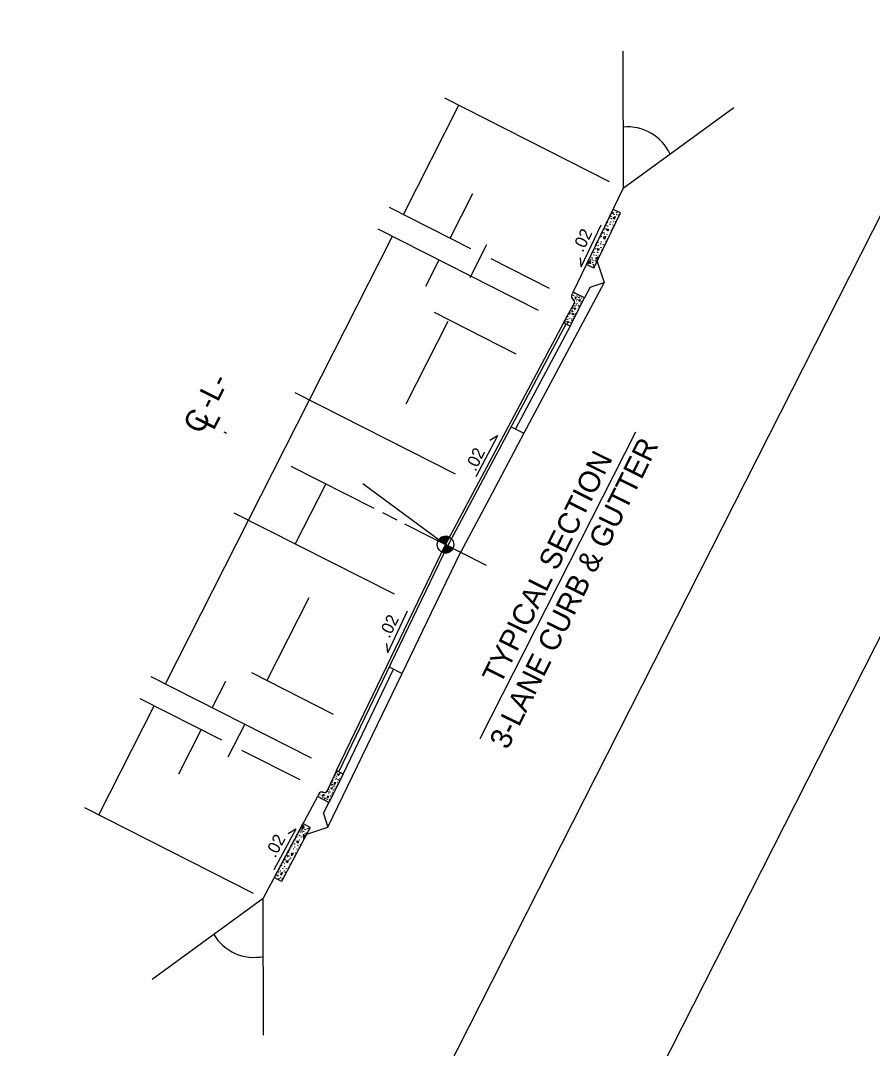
# Model space of a CAD drawing. Extents: x 1974386 to 1979988, y 776712 to 784860.
# Drawn here: x 1977212 to 1977629, y 778805 to 779309 of the extents above; entities that cross this region are included whole.
import ezdxf

# ---------------------------------------------------------------- set-up
doc = ezdxf.new("R2010")
doc.units = 0
for name, color, linetype in [('Default', 7, 'Continuous'), ('Old_Level_1', 7, 'Continuous'), ('Old_Level_2', 7, 'Continuous'), ('Old_Level_4', 7, 'Continuous')]:
    doc.layers.add(name, color=color, linetype=linetype)

msp = doc.modelspace()

# ---------------------------------------------------------------- linework, layer by layer
at = {"layer": 'Default'}
msp.add_lwpolyline([(1978009.96, 784859.92), (1974385.88, 777715.09), (1976364.02, 776711.71), (1979988.11, 783856.54)], close=True, dxfattribs=at)
at = {"layer": 'Old_Level_1'}
for p, q in [((1977506.9, 779294.21), (1977507.03, 779226.87)), ((1977419.44, 779271.28), (1977500.16, 779230.36)), ((1977399.38, 779214.18), (1977426.52, 779267.69)), ((1977561.2, 779266.39), (1977507.03, 779226.87)), ((1977482.53, 779176.05), (1977507.03, 779226.87)), ((1977422.32, 779202.55), (1977433.4, 779224.41)), ((1977392.3, 779217.77), (1977432.24, 779197.52)), ((1977489.03, 779189.57), (1977502.04, 779216.61)), ((1977492.71, 779187.8), (1977505.71, 779214.85)), ((1977505.71, 779214.85), (1977502.04, 779216.61)), ((1977386.88, 779207.07), (1977465.34, 779167.28)), ((1977353.26, 779123.21), (1977393.96, 779203.48)), ((1977432.06, 779183.23), (1977440.28, 779199.45)), ((1977410.39, 779179.02), (1977416.89, 779191.85)), ((1977442.18, 779192.48), (1977470.77, 779177.99)), ((1977492.71, 779187.8), (1977489.03, 779189.57)), ((1977494.3, 779191.12), (1977497.7, 779180.75)), ((1977497.7, 779180.75), (1977458.38, 779106.9)), ((1977490.91, 779178.53), (1977497.7, 779180.75)), ((1977481.82, 779174.66), (1977482.53, 779176.05)), ((1977488.09, 779173.23), (1977482.53, 779176.05)), ((1977490.91, 779178.53), (1977488.09, 779173.23)), ((1977477.81, 779160.96), (1977483.04, 779170.5)), ((1977481.04, 779159.32), (1977488.09, 779173.23)), ((1977414.4, 779166.2), (1977454.49, 779145.88)), ((1977400.68, 779121.35), (1977421.2, 779161.83)), ((1977477.81, 779160.96), (1977420, 779052.37)), ((1977478.92, 779160.37), (1977421.06, 779051.94)), ((1977481.04, 779159.32), (1977454.25, 779109)), ((1977481.04, 779159.32), (1977477.81, 779160.96)), ((1977346.18, 779126.8), (1977424.64, 779087.01)), ((1977323.41, 779064.34), (1977353.26, 779123.21)), ((1977452.09, 779110.09), (1977458.38, 779106.9)), ((1977312.79, 779106.73), (1977311.45, 779107.4)), ((1977436.95, 778957.34), (1977513.18, 779107.62)), ((1977458.38, 779106.9), (1977442.79, 779077.62)), ((1977344.18, 779090.81), (1977384.8, 779070.21)), ((1977361.27, 779082.15), (1977346.34, 779052.71)), ((1977379.4, 779082.27), (1977420, 779052.37)), ((1977442.79, 779077.62), (1977427.28, 779048.49)), ((1977282.71, 778984.07), (1977323.41, 779064.34)), ((1977316.33, 779067.93), (1977394.79, 779028.15)), ((1977389.02, 779068.07), (1977396.06, 779064.5)), ((1977399.9, 779062.55), (1977439.93, 779042.26)), ((1977420, 779052.37), (1977416.38, 779054.2)), ((1977421.83, 779055.98), (1977420, 779052.37)), ((1977366.57, 778941.55), (1977420, 779052.37)), ((1977367.69, 778940.98), (1977421.06, 779051.94)), ((1977413.09, 779019.05), (1977427.43, 779048.78)), ((1977418.17, 779048.75), (1977420, 779052.37)), ((1977423.6, 779050.53), (1977420, 779052.37)), ((1977420, 779052.37), (1977423.6, 779050.53)), ((1977352.97, 779026.24), (1977332.45, 778985.76)), ((1977398.69, 778989.17), (1977413.09, 779019.05)), ((1977324.86, 778989.6), (1977364.95, 778969.28)), ((1977362.35, 778913.82), (1977398.69, 778989.17)), ((1977369.79, 778939.91), (1977394.55, 778991.27)), ((1977392.4, 778992.36), (1977398.69, 778989.17)), ((1977275.63, 778987.66), (1977354.09, 778947.87)), ((1977312.14, 778985.27), (1977305.64, 778972.44)), ((1977250.15, 778919.85), (1977277.28, 778973.37)), ((1977270.2, 778976.96), (1977310.14, 778956.71)), ((1977321.59, 778964.35), (1977313.37, 778948.14)), ((1977300.22, 778961.74), (1977289.13, 778939.88)), ((1977320.08, 778951.67), (1977348.67, 778937.17)), ((1977366.57, 778941.55), (1977361.96, 778931.7)), ((1977369.79, 778939.91), (1977362.74, 778926.01)), ((1977369.79, 778939.91), (1977366.57, 778941.55)), ((1977357.18, 778928.83), (1977330.66, 778879.03)), ((1977357.88, 778930.22), (1977357.18, 778928.83)), ((1977362.74, 778926.01), (1977357.18, 778928.83)), ((1977243.07, 778923.44), (1977325.78, 778881.51)), ((1977360.13, 778920.6), (1977362.74, 778926.01)), ((1977360.13, 778920.6), (1977362.35, 778913.82)), ((1977350.11, 778915.59), (1977335.99, 778889.12)), ((1977353.71, 778913.67), (1977339.58, 778887.2)), ((1977353.71, 778913.67), (1977350.11, 778915.59)), ((1977351.98, 778910.42), (1977362.35, 778913.82)), ((1977339.58, 778887.2), (1977335.98, 778889.12)), ((1977276.26, 778839.34), (1977330.66, 778879.03)), ((1977330.8, 778811.97), (1977330.66, 778879.03))]:
    msp.add_line(p, q, dxfattribs=at)
for points in [[(1977416.4, 779054.23), (1977416.4, 779054.23), (1977420.01, 779052.4)], [(1977416.44, 779054.3), (1977420.05, 779052.47)], [(1977416.48, 779054.37), (1977420.09, 779052.54)], [(1977416.52, 779054.44), (1977420.12, 779052.62)], [(1977416.56, 779054.51), (1977420.16, 779052.69)], [(1977416.61, 779054.58), (1977420.2, 779052.76)], [(1977416.65, 779054.65), (1977420.23, 779052.83)], [(1977416.7, 779054.72), (1977420.27, 779052.9)], [(1977416.74, 779054.78), (1977420.31, 779052.98)], [(1977416.79, 779054.85), (1977420.34, 779053.05)], [(1977416.85, 779054.91), (1977420.38, 779053.12)], [(1977416.9, 779054.98), (1977420.42, 779053.19)], [(1977416.95, 779055.04), (1977420.45, 779053.27)], [(1977417.01, 779055.1), (1977420.49, 779053.34)], [(1977417.07, 779055.16), (1977420.53, 779053.41)], [(1977417.13, 779055.22), (1977420.56, 779053.48)], [(1977417.19, 779055.28), (1977420.6, 779053.55)], [(1977417.25, 779055.34), (1977420.64, 779053.63)], [(1977417.32, 779055.4), (1977420.67, 779053.7)], [(1977417.39, 779055.46), (1977420.71, 779053.77)], [(1977417.45, 779055.51), (1977420.75, 779053.84)], [(1977417.52, 779055.57), (1977420.78, 779053.92)], [(1977417.59, 779055.62), (1977420.82, 779053.99)], [(1977417.67, 779055.68), (1977420.86, 779054.06)], [(1977417.75, 779055.73), (1977420.89, 779054.13)], [(1977417.82, 779055.78), (1977420.93, 779054.2)], [(1977417.9, 779055.83), (1977420.97, 779054.28)], [(1977417.98, 779055.88), (1977421, 779054.35)], [(1977418.07, 779055.93), (1977421.04, 779054.42)], [(1977418.16, 779055.97), (1977421.08, 779054.49)], [(1977418.25, 779056.02), (1977421.11, 779054.57)], [(1977418.34, 779056.06), (1977421.15, 779054.64)], [(1977418.44, 779056.1), (1977421.19, 779054.71)], [(1977418.54, 779056.14), (1977421.22, 779054.78)], [(1977418.64, 779056.18), (1977421.26, 779054.86)], [(1977418.75, 779056.22), (1977421.29, 779054.93)], [(1977418.86, 779056.25), (1977421.33, 779055)], [(1977418.98, 779056.28), (1977421.37, 779055.07)], [(1977419.1, 779056.31), (1977421.4, 779055.14)], [(1977419.23, 779056.34), (1977421.44, 779055.22)], [(1977419.36, 779056.36), (1977421.48, 779055.29)], [(1977419.5, 779056.38), (1977421.51, 779055.36)], [(1977419.65, 779056.4), (1977421.55, 779055.43)], [(1977419.81, 779056.41), (1977421.59, 779055.51)], [(1977419.97, 779056.42), (1977421.62, 779055.58)], [(1977420.16, 779056.41), (1977421.66, 779055.65)], [(1977420.37, 779056.4), (1977421.7, 779055.72)], [(1977420.6, 779056.37), (1977421.73, 779055.79)], [(1977420.89, 779056.31), (1977421.77, 779055.87)], [(1977421.29, 779056.2), (1977421.81, 779055.94)], [(1977418.17, 779048.77), (1977418.57, 779048.57)], [(1977418.21, 779048.84), (1977419.03, 779048.43)], [(1977418.25, 779048.92), (1977419.32, 779048.37)], [(1977418.28, 779048.99), (1977419.58, 779048.33)], [(1977418.32, 779049.06), (1977419.78, 779048.32)], [(1977418.36, 779049.13), (1977419.97, 779048.31)], [(1977418.39, 779049.2), (1977420.14, 779048.32)], [(1977418.43, 779049.28), (1977420.31, 779048.32)], [(1977418.47, 779049.35), (1977420.46, 779048.34)], [(1977418.5, 779049.42), (1977420.6, 779048.36)], [(1977418.54, 779049.49), (1977420.73, 779048.38)], [(1977418.58, 779049.57), (1977420.86, 779048.41)], [(1977418.61, 779049.64), (1977420.98, 779048.44)], [(1977418.65, 779049.71), (1977421.1, 779048.47)], [(1977418.69, 779049.78), (1977421.21, 779048.5)], [(1977418.72, 779049.85), (1977421.32, 779048.54)], [(1977418.76, 779049.93), (1977421.42, 779048.58)], [(1977418.8, 779050), (1977421.53, 779048.61)], [(1977418.83, 779050.07), (1977421.63, 779048.65)], [(1977418.87, 779050.14), (1977421.72, 779048.7)], [(1977418.91, 779050.22), (1977421.81, 779048.74)], [(1977418.94, 779050.29), (1977421.9, 779048.79)], [(1977418.98, 779050.36), (1977421.98, 779048.84)], [(1977419.02, 779050.43), (1977422.07, 779048.89)], [(1977419.05, 779050.5), (1977422.15, 779048.93)], [(1977419.09, 779050.58), (1977422.23, 779048.99)], [(1977419.13, 779050.65), (1977422.3, 779049.04)], [(1977419.16, 779050.72), (1977422.38, 779049.09)], [(1977419.2, 779050.79), (1977422.45, 779049.15)], [(1977419.24, 779050.87), (1977422.52, 779049.2)], [(1977419.27, 779050.94), (1977422.59, 779049.26)], [(1977419.31, 779051.01), (1977422.66, 779049.31)], [(1977419.35, 779051.08), (1977422.72, 779049.37)], [(1977419.38, 779051.15), (1977422.79, 779049.43)], [(1977419.42, 779051.23), (1977422.85, 779049.49)], [(1977419.46, 779051.3), (1977422.91, 779049.55)], [(1977419.49, 779051.37), (1977422.96, 779049.61)], [(1977419.53, 779051.44), (1977423.02, 779049.67)], [(1977419.57, 779051.52), (1977423.07, 779049.74)], [(1977419.6, 779051.59), (1977423.13, 779049.8)], [(1977419.64, 779051.66), (1977423.18, 779049.87)], [(1977419.68, 779051.73), (1977423.23, 779049.93)], [(1977419.71, 779051.8), (1977423.28, 779050)], [(1977419.75, 779051.88), (1977423.33, 779050.06)], [(1977419.78, 779051.95), (1977423.37, 779050.13)], [(1977419.82, 779052.02), (1977423.42, 779050.2)], [(1977419.86, 779052.09), (1977423.46, 779050.27)], [(1977419.89, 779052.17), (1977423.5, 779050.34)], [(1977419.93, 779052.24), (1977423.54, 779050.41)], [(1977419.97, 779052.31), (1977423.58, 779050.48), (1977423.58, 779050.48)]]:
    msp.add_lwpolyline(points, dxfattribs=at)
msp.add_circle((1977419.99, 779052.36), 4.05, dxfattribs=at)
for centre, radius, start, end in [((1977509.22, 779234.09), 22.94, 24.6899, 95.6239), ((1977483.21, 779173.95), 1.56, 153.1133, 240.3562), ((1977481.67, 779171.24), 1.56, 331.2849, 60.3562), ((1977419.99, 779052.36), 4.05, 63.1038, 153.1038), ((1977419.99, 779052.36), 4.05, 243.1038, 333.1038), ((1977359.27, 778929.51), 1.56, 65.8705, 153.1133), ((1977360.55, 778932.36), 1.56, 245.8705, 334.9418), ((1977326.13, 778872.99), 22.94, 210.6027, 281.5371)]:
    msp.add_arc(centre, radius, start, end, dxfattribs=at)
at = {"layer": 'Old_Level_2'}
for p, q in [((1977502.11, 779212.67), (1977503.08, 779213.2)), ((1977502.77, 779211.76), (1977502.11, 779212.67)), ((1977503.08, 779213.2), (1977502.77, 779211.76)), ((1977486.42, 779188.49), (1977496.16, 779209.02)), ((1977499.5, 779205.99), (1977498.89, 779207.11)), ((1977498.89, 779207.11), (1977499.9, 779206.95)), ((1977499.9, 779206.95), (1977499.5, 779205.99)), ((1977497.43, 779202.95), (1977498.4, 779203.47)), ((1977498.09, 779202.03), (1977497.43, 779202.95)), ((1977498.4, 779203.47), (1977498.09, 779202.03)), ((1977494.82, 779196.26), (1977494.22, 779197.38)), ((1977494.22, 779197.38), (1977495.23, 779197.22)), ((1977495.23, 779197.22), (1977494.82, 779196.26)), ((1977486.42, 779188.49), (1977486.06, 779192.94)), ((1977490.09, 779191.04), (1977491.06, 779191.56)), ((1977490.75, 779190.12), (1977490.09, 779191.04)), ((1977491.06, 779191.56), (1977490.75, 779190.12)), ((1977493.85, 779192.87), (1977494.81, 779193.39)), ((1977494.5, 779191.95), (1977493.85, 779192.87)), ((1977494.81, 779193.39), (1977494.5, 779191.95)), ((1977483.98, 779173.67), (1977483.32, 779172.97)), ((1977483.32, 779172.97), (1977483.85, 779172.81)), ((1977483.85, 779172.81), (1977483.98, 779173.67)), ((1977485.34, 779172.14), (1977486.02, 779172.48)), ((1977485.78, 779171.49), (1977485.34, 779172.14)), ((1977486.02, 779172.48), (1977485.78, 779171.49)), ((1977481.96, 779165.47), (1977482.64, 779165.81)), ((1977482.4, 779164.82), (1977481.96, 779165.47)), ((1977482.64, 779165.81), (1977482.4, 779164.82)), ((1977483.44, 779167.55), (1977483.03, 779168.33)), ((1977483.03, 779168.33), (1977483.73, 779168.2)), ((1977483.73, 779168.2), (1977483.44, 779167.55)), ((1977480.06, 779160.87), (1977479.65, 779161.66)), ((1977479.65, 779161.66), (1977480.35, 779161.53)), ((1977480.35, 779161.53), (1977480.06, 779160.87)), ((1977445.46, 779105.64), (1977434.76, 779085.6)), ((1977445.46, 779105.64), (1977441.68, 779103.28)), ((1977391.63, 778999.34), (1977401.36, 779019.87)), ((1977391.63, 778999.34), (1977391.27, 779003.79)), ((1977367.96, 778939.79), (1977367.09, 778939.66)), ((1977367.09, 778939.66), (1977367.6, 778939.17)), ((1977367.6, 778939.17), (1977367.96, 778939.79)), ((1977364.58, 778933.12), (1977363.71, 778932.99)), ((1977363.71, 778932.99), (1977364.22, 778932.5)), ((1977364.22, 778932.5), (1977364.58, 778933.12)), ((1977366.16, 778935.57), (1977365.38, 778935.54)), ((1977365.38, 778935.54), (1977365.5, 778934.79)), ((1977365.5, 778934.79), (1977366.16, 778935.57)), ((1977359.95, 778929.06), (1977360.13, 778930.01)), ((1977360.57, 778929.67), (1977359.95, 778929.06)), ((1977360.13, 778930.01), (1977360.57, 778929.67)), ((1977362.78, 778928.9), (1977362, 778928.87)), ((1977362, 778928.87), (1977362.12, 778928.12)), ((1977362.12, 778928.12), (1977362.78, 778928.9)), ((1977346.67, 778912.86), (1977335.86, 778892.87)), ((1977346.67, 778912.86), (1977342.87, 778910.52)), ((1977350.69, 778913.88), (1977349.56, 778913.87)), ((1977349.56, 778913.87), (1977349.71, 778912.78)), ((1977349.71, 778912.78), (1977350.69, 778913.88)), ((1977351.43, 778909.77), (1977350.3, 778909.76)), ((1977350.3, 778909.76), (1977350.45, 778908.67)), ((1977350.45, 778908.67), (1977351.43, 778909.77)), ((1977348.14, 778906.96), (1977346.88, 778906.79)), ((1977346.88, 778906.79), (1977347.6, 778906.07)), ((1977347.6, 778906.07), (1977348.14, 778906.96)), ((1977343.05, 778897.44), (1977341.79, 778897.27)), ((1977342.52, 778896.55), (1977343.05, 778897.44)), ((1977345.42, 778900.92), (1977344.29, 778900.91)), ((1977344.29, 778900.91), (1977344.44, 778899.82)), ((1977344.44, 778899.82), (1977345.42, 778900.92)), ((1977341.79, 778897.27), (1977342.52, 778896.55)), ((1977340.34, 778891.4), (1977339.21, 778891.39)), ((1977339.21, 778891.39), (1977339.36, 778890.3)), ((1977339.36, 778890.3), (1977340.34, 778891.4))]:
    msp.add_line(p, q, dxfattribs=at)
for centre, radius in [((1977501.82, 779214.68), 0.0693), ((1977502.29, 779214.99), 0.0693), ((1977503.84, 779215.01), 0.0693), ((1977499.06, 779210.53), 0.0693), ((1977499.39, 779210.21), 0.0693), ((1977500.25, 779212.42), 0.0693), ((1977500.87, 779210.43), 0.0693), ((1977501.09, 779213.17), 0.0693), ((1977501.25, 779212.09), 0.0693), ((1977502.34, 779210.68), 0.0693), ((1977502.51, 779214.18), 0.0693), ((1977503.22, 779210.66), 0.0693), ((1977503.83, 779214.09), 0.0693), ((1977504.18, 779211.85), 0.0693), ((1977504.78, 779213.91), 0.0693), ((1977497.14, 779204.95), 0.0693), ((1977497.61, 779205.26), 0.0693), ((1977498.07, 779207.01), 0.0693), ((1977498.5, 779208.67), 0.0693), ((1977499.16, 779205.28), 0.0693), ((1977499.4, 779208.51), 0.0693), ((1977500.62, 779209.34), 0.0693), ((1977501.24, 779206.31), 0.0693), ((1977501.95, 779209.03), 0.0693), ((1977502.19, 779207.82), 0.0693), ((1977494.38, 779200.8), 0.0693), ((1977494.71, 779200.48), 0.0693), ((1977495.57, 779202.7), 0.0693), ((1977495.94, 779199.62), 0.0693), ((1977496.19, 779200.7), 0.0693), ((1977496.41, 779203.44), 0.0693), ((1977497.83, 779204.46), 0.0693), ((1977498.55, 779200.94), 0.0693), ((1977499.16, 779204.36), 0.0693), ((1977499.5, 779202.12), 0.0693), ((1977492.76, 779195.6), 0.0693), ((1977493.4, 779197.28), 0.0693), ((1977493.82, 779198.94), 0.0693), ((1977494.48, 779195.56), 0.0693), ((1977494.72, 779198.78), 0.0693), ((1977496.17, 779197.87), 0.0693), ((1977496.56, 779196.58), 0.0693), ((1977497.27, 779199.31), 0.0693), ((1977497.51, 779198.1), 0.0693), ((1977489.85, 779190.71), 0.0693), ((1977489.97, 779190.05), 0.0693), ((1977490.93, 779190.19), 0.0693), ((1977491.19, 779192.11), 0.0693), ((1977491.69, 779192.92), 0.0693), ((1977492.03, 779190.54), 0.0693), ((1977492.09, 779192.39), 0.0693), ((1977492.29, 779191.52), 0.0693), ((1977492.43, 779189.52), 0.0693), ((1977492.67, 779194.26), 0.0693), ((1977493.55, 779191.52), 0.0693), ((1977493.6, 779192.54), 0.0693), ((1977493.7, 779190.9), 0.0693), ((1977493.83, 779194.15), 0.0693), ((1977495.27, 779193.95), 0.0693), ((1977492.41, 779188.81), 0.0693), ((1977482.61, 779174.52), 0.048), ((1977483.47, 779175.3), 0.048), ((1977485.13, 779174.65), 0.048), ((1977481.84, 779173.45), 0.048), ((1977482.57, 779172.39), 0.048), ((1977482.78, 779169.41), 0.048), ((1977483.2, 779170.69), 0.048), ((1977483.42, 779170.47), 0.048), ((1977483.45, 779173.75), 0.048), ((1977484.05, 779171.99), 0.048), ((1977484.26, 779169.85), 0.048), ((1977484.38, 779174.16), 0.048), ((1977484.45, 779170.6), 0.048), ((1977484.64, 779172.49), 0.048), ((1977485.17, 779173.53), 0.048), ((1977485.18, 779169.62), 0.048), ((1977485.5, 779173.74), 0.048), ((1977485.64, 779173.18), 0.048), ((1977485.94, 779169.61), 0.048), ((1977486.09, 779170.73), 0.048), ((1977486.56, 779173.09), 0.048), ((1977486.57, 779173.73), 0.048), ((1977486.76, 779171.53), 0.048), ((1977487.27, 779172.31), 0.048), ((1977487.96, 779173.37), 0.048), ((1977480.67, 779165.32), 0.048), ((1977481.26, 779165.82), 0.048), ((1977481.75, 779167.98), 0.048), ((1977481.79, 779166.86), 0.048), ((1977482.12, 779167.06), 0.048), ((1977482.26, 779166.5), 0.048), ((1977482.46, 779168.27), 0.048), ((1977483.18, 779166.42), 0.048), ((1977483.19, 779167.06), 0.048), ((1977483.38, 779164.86), 0.048), ((1977483.4, 779169.29), 0.048), ((1977483.89, 779165.64), 0.048), ((1977484.58, 779166.7), 0.048), ((1977484.65, 779167.74), 0.048), ((1977485.33, 779168.77), 0.048), ((1977478.37, 779161.31), 0.048), ((1977478.66, 779162.12), 0.048), ((1977479.08, 779161.6), 0.048), ((1977479.4, 779162.74), 0.048), ((1977479.81, 779160.39), 0.048), ((1977479.82, 779164.02), 0.048), ((1977480.02, 779162.62), 0.048), ((1977480.04, 779163.8), 0.048), ((1977480.88, 779163.18), 0.048), ((1977481.07, 779163.93), 0.048), ((1977481.2, 779160.03), 0.048), ((1977481.26, 779161.07), 0.048), ((1977481.79, 779162.94), 0.048), ((1977481.94, 779162.1), 0.048), ((1977482.56, 779162.94), 0.048), ((1977482.7, 779164.06), 0.048), ((1977365.28, 778938.12), 0.048), ((1977365.59, 778938.08), 0.048), ((1977366.06, 778939.22), 0.048), ((1977366.13, 778940.18), 0.048), ((1977366.53, 778938.79), 0.048), ((1977366.59, 778937.77), 0.048), ((1977366.61, 778940.9), 0.048), ((1977366.8, 778940.15), 0.048), ((1977368.21, 778940.28), 0.048), ((1977368.52, 778938.7), 0.048), ((1977369.32, 778939.37), 0.048), ((1977363.23, 778934.23), 0.048), ((1977363.42, 778933.48), 0.048), ((1977364.16, 778934.86), 0.048), ((1977364.19, 778934.47), 0.048), ((1977364.68, 778935.9), 0.048), ((1977364.72, 778934.69), 0.048), ((1977364.74, 778936.67), 0.048), ((1977364.82, 778933.61), 0.048), ((1977365.33, 778934), 0.048), ((1977365.93, 778932.7), 0.048), ((1977366.09, 778937.17), 0.048), ((1977366.38, 778933.88), 0.048), ((1977366.71, 778934.75), 0.048), ((1977366.96, 778935.78), 0.048), ((1977367.32, 778937.17), 0.048), ((1977367.77, 778936.55), 0.048), ((1977368.08, 778937.54), 0.048), ((1977358.34, 778928.51), 0.048), ((1977358.46, 778929.67), 0.048), ((1977358.87, 778930.92), 0.048), ((1977359.58, 778929.45), 0.048), ((1977359.8, 778928.45), 0.048), ((1977359.84, 778927.55), 0.048), ((1977360.15, 778930.96), 0.048), ((1977360.77, 778928.19), 0.048), ((1977360.8, 778927.8), 0.048), ((1977361.3, 778929.22), 0.048), ((1977361.34, 778928.02), 0.048), ((1977361.35, 778930), 0.048), ((1977361.9, 778931.45), 0.048), ((1977362.21, 778931.41), 0.048), ((1977362.68, 778932.55), 0.048), ((1977362.71, 778930.5), 0.048), ((1977363.15, 778932.12), 0.048), ((1977363.2, 778931.09), 0.048), ((1977363.32, 778928.08), 0.048), ((1977363.57, 778929.1), 0.048), ((1977363.93, 778930.49), 0.048), ((1977364.39, 778929.88), 0.048), ((1977364.7, 778930.87), 0.048), ((1977365.14, 778932.03), 0.048), ((1977361.44, 778926.94), 0.048), ((1977361.95, 778927.33), 0.048), ((1977362.55, 778926.03), 0.048), ((1977363, 778927.21), 0.048), ((1977349.68, 778914.26), 0.0693), ((1977350.29, 778914.55), 0.0693), ((1977350.73, 778913.7), 0.0693), ((1977351.11, 778912.6), 0.0693), ((1977352.16, 778912.88), 0.0693), ((1977352.72, 778913.31), 0.0693), ((1977346.47, 778907.52), 0.0693), ((1977347.45, 778909.02), 0.0693), ((1977348.48, 778909.89), 0.0693), ((1977348.51, 778907.66), 0.0693), ((1977348.99, 778911.47), 0.0693), ((1977349.26, 778909.02), 0.0693), ((1977349.34, 778912.35), 0.0693), ((1977349.65, 778911.46), 0.0693), ((1977350.27, 778907.97), 0.0693), ((1977350.42, 778910.15), 0.0693), ((1977350.46, 778911.81), 0.0693), ((1977351.22, 778910.79), 0.0693), ((1977351.8, 778911.04), 0.0693), ((1977343.39, 778902.56), 0.0693), ((1977344.22, 778904.64), 0.0693), ((1977344.67, 778904.56), 0.0693), ((1977345.37, 778903.24), 0.0693), ((1977345.38, 778906.19), 0.0693), ((1977346.04, 778905.56), 0.0693), ((1977346.09, 778904.08), 0.0693), ((1977347.13, 778903.19), 0.0693), ((1977347.64, 778904.93), 0.0693), ((1977348.25, 778903.72), 0.0693), ((1977348.91, 778905.38), 0.0693), ((1977341.39, 778897.99), 0.0693), ((1977342.5, 778899.96), 0.0693), ((1977342.53, 778899.4), 0.0693), ((1977343.29, 778901.44), 0.0693), ((1977343.31, 778899.7), 0.0693), ((1977343.42, 778898.14), 0.0693), ((1977344.16, 778898.68), 0.0693), ((1977346.18, 778899.73), 0.0693), ((1977346.57, 778901.2), 0.0693), ((1977338.31, 778893.04), 0.0693), ((1977339.14, 778895.11), 0.0693), ((1977339.17, 778892.43), 0.0693), ((1977339.59, 778895.04), 0.0693), ((1977340.28, 778893.72), 0.0693), ((1977340.3, 778896.67), 0.0693), ((1977340.95, 778892.38), 0.0693), ((1977340.96, 778896.04), 0.0693), ((1977341.01, 778894.56), 0.0693), ((1977342.05, 778893.67), 0.0693), ((1977343.17, 778894.19), 0.0693), ((1977343.83, 778895.85), 0.0693), ((1977337.42, 778890.44), 0.0693), ((1977337.45, 778889.87), 0.0693), ((1977338.21, 778891.92), 0.0693), ((1977338.22, 778890.18), 0.0693), ((1977338.34, 778888.61), 0.0693), ((1977339.08, 778889.16), 0.0693), ((1977339.79, 778888.5), 0.0693), ((1977341.1, 778890.21), 0.0693), ((1977341.49, 778891.68), 0.0693)]:
    msp.add_circle(centre, radius, dxfattribs=at)
for centre, start, end in [((1977482.04, 779168.79), 233.9502, 67.5011), ((1977362.75, 778933.51), 238.7255, 72.2765)]:
    msp.add_arc(centre, 0.048, start, end, dxfattribs=at)
at = {"layer": 'Old_Level_4'}
msp.add_lwpolyline([(1977508, 778760.75), (1977825.85, 779387.39), (1978039.36, 779279.09), (1977721.51, 778652.45)], close=True, dxfattribs=at)

# ---------------------------------------------------------------- texts
at = {"layer": 'Old_Level_2'}
for s, height, rotation, p in [('.02', 6, 64.3049, (1977487.28, 779195.21)), ('-L-', 10.461, 63.2916, (1977306.26, 779117.66)), ('C', 10.8, 63.1133, (1977300.52, 779105.93)), ('L', 10.8, 63.0602, (1977306.37, 779107.83)), ('3-LANE CURB & GUTTER ', 10.4606, 63.6527, (1977450.4, 778951.43)), ('.02 ', 6, 64.3049, (1977434.69, 779087.84)), ('TYPICAL SECTION', 10.4606, 63.6527, (1977446.9, 778983.32)), ('.02', 6, 64.3049, (1977392.49, 779006.06)), ('.02', 6, 61.9217, (1977336.55, 778898.45))]:
    msp.add_text(s, height=height, rotation=rotation, dxfattribs=at).set_placement(p)

doc.saveas('drawing.dxf')
